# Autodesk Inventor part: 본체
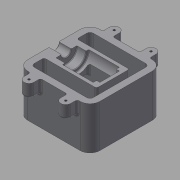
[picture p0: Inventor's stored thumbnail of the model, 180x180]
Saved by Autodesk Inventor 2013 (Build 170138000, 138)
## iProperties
Created: 2018-01
Part Number: 본체
Material: 일반
Document SubType Name: Modeling
Designer: Administrator
Density: 1 g/cm^3
Author: Administrator
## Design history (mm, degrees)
sketch "스케치1"
  geometry: L1 (-55, 55)-(55, 55); L2 (55, 55)-(55, -55); L3 (55, -55)-(-55, -55); L4 (-55, -55)-(-55, 55); L5 (-55, 55)-(55, -55); L6 (55, 55)-(-55, -55); 2 further points
  constraints: 12 end point, 4 midpoint, 2 parallel, 1 horizontal, 1 perpendicular
  dimensions: "d0" = 110 distance of L2.end L3.end; "d1" = 110 distance of L1.end L2.end
extrude "돌출1" new body sketch "스케치1" distance "d2" = 65; taper "d3" = 0 deg
fillet "모깎기1" dims "d4" = 15
sketch "스케치3"
  geometry: L1 (55, 40)-(55, -40) reference; L2 (40, -55)-(-40, -55) reference; L3 (-55, -40)-(-55, 40) reference; L4 (-40, 55)-(40, 55) reference; L5 (45, 40)-(45, -40); L6 (40, -45)-(-40, -45); L7 (-45, -40)-(-45, 40); L8 (-40, 45)-(40, 45); A1 r 15 centre (40, 40) between (55, 40) and (40, 55) reference; A2 r 15 centre (40, -40) between (40, -55) and (55, -40) reference; A3 r 15 centre (-40, -40) between (-55, -40) and (-40, -55) reference; A4 r 15 centre (-40, 40) between (-40, 55) and (-55, 40) reference; A5 r 5 centre (40, 40) between (45, 40) and (40, 45); A6 r 5 centre (40, -40) between (40, -45) and (45, -40); A7 r 5 centre (-40, -40) between (-45, -40) and (-40, -45); A8 r 5 centre (-40, 40) between (-40, 45) and (-45, 40); 1 further point
  constraints: 8 end point, 8 point on circle, 4 centre point, 7 other
  dimensions: "d5" = 10 distance between parallel lines of L1 L5
extrude "돌출2" cut sketch "스케치3" stored distance "d6" = 65; taper "d7" = 0 deg
sketch "스케치5"
  geometry: L1 (-35.5, 55)-(-35.5, 65); L2 (40, 55)-(-40, 55) reference; L3 (-20.5, 65)-(-20.5, 55); L4 (-55, 40)-(-55, -40) reference; L5 (0, 32.443)-(0, -32.443); L6 (35.5, 55)-(35.5, 65); L7 (20.5, 65)-(20.5, 55); L8 (-28, 0)-(28, 0); L9 (-40, -55)-(40, -55) reference; L10 (-35.5, 55)-(-20.5, 55); L11 (20.5, 55)-(35.5, 55); L12 (-20.5, -65)-(-20.5, -55); L13 (-35.5, -55)-(-35.5, -65); L14 (20.5, -65)-(20.5, -55); L15 (35.5, -55)-(35.5, -65); L16 (20.5, -55)-(35.5, -55); L17 (-35.5, -55)-(-20.5, -55); A1 r 7.5 centre (-28, 65) between (-20.5, 65) and (-35.5, 65); A2 r 7.5 centre (28, 65) between (35.5, 65) and (20.5, 65); A3 r 7.5 centre (-28, -65) between (-35.5, -65) and (-20.5, -65); A4 r 7.5 centre (28, -65) between (20.5, -65) and (35.5, -65); 2 further points
  constraints: 28 end point, 15 symmetric about line, 8 point on circle, 4 centre point, 3 parallel, 2 midpoint, 2 perpendicular, 2 point on line, 2 tangent, 1 coincident, 3 other
  dimensions: "d14" = 7.5 radius of A1; "d15" = 27 distance from line of A1.centre L4; "d16" = 10 distance of L3.start L3.end; "d17" = 64.88594 distance of L5.start L5.end; "d18" = 56 distance of L8.start L8.end
extrude "돌출4" join sketch "스케치5" distance "d19" = 20; taper "d20" = 0 deg
sketch "스케치6"
  geometry: A1 r 7.5 centre (-28, 65) between (-20.5, 65) and (-35.5, 65) reference; A2 r 7.5 centre (28, 65) between (35.5, 65) and (20.5, 65) reference; A3 r 7.5 centre (28, -65) between (20.5, -65) and (35.5, -65) reference; A4 r 7.5 centre (-28, -65) between (-35.5, -65) and (-20.5, -65) reference; 5 further points
  constraints: 4 coincident
hole "구멍1" sketch "스케치6" at (-28, 65), (28, 65), (-28, -65), (28, -65) diameter "d21" = 3.242; stored, may be unused: countersink angle "d25" = 90 deg, drill point angle "d27" = 118 deg; dims "d22" = 9, "d23" = 4, "d24" = 2, "d26" = 11
sketch "스케치8"
  geometry: L1 (-45, 25)-(35, 25); L2 (-45, -40)-(-45, 40) reference; L3 (35, 25)-(35, -25); L4 (35, -25)-(-45, -25); L5 (55, -40)-(55, 40) reference; L6 (-45, 25)-(-45, -25); 2 further points
  constraints: 8 end point, 2 perpendicular, 2 point on line, 1 collinear, 1 horizontal alignment, 1 midpoint, 1 parallel
  dimensions: "d28" = 20 distance between parallel lines of L5 L3; "d29" = 50 distance between parallel lines of L4 L1
extrude "돌출5" join sketch "스케치8" distance "d30" = 65; taper "d31" = 0 deg
sketch "스케치12"
  geometry: L1 (-55, 0)-(39.453, 0); L2 (-55, 40)-(-55, -40) reference; L3 (-45, 25)-(35, 25) reference; L4 (35, -25)-(-45, -25) reference; L5 (35, 25)-(35, -25) reference; L6 (-55, 7.5)-(-36, 7.5); L7 (-55, -40)-(-55, 40) reference; L8 (-36, 7.5)-(-36, 16); L9 (-36, 16)-(-22, 16); L10 (-22, 16)-(-22, 20); L11 (-22, 20)-(25, 20); L12 (25, 20)-(25, 15); L13 (25, 15)-(30, 15); L14 (30, 15)-(30, 0); L15 (-55, 7.5)-(-55, 0); 2 further points
  constraints: 20 end point, 5 parallel, 3 perpendicular, 3 point on line, 1 coincident, 1 collinear, 1 horizontal, 1 midpoint
  dimensions: "d32" = 15 diameter of L6 L1; "d34" = 32 diameter of L9 L1; "d35" = 40 diameter of L11 L1; "d37" = 30 diameter of L13 L1; "d38" = 19 distance of L6.start L6.end; "d39" = 14 distance of L8.end L9.end; "d40" = 47 distance of L10.end L11.end; "d41" = 5 distance of L12.end L13.end
revolve "회전1" sketch "스케치12" stored, may be unused: angle "d42" = 90 deg
sketch "스케치16"
  geometry: L1 (-20, 58.93)-(-20, 31.157); L2 (-35, 65)-(-35, 0) reference; L3 (-20, 31.157)-(55, 11.061); L4 (17, 58.93)-(17, 39.243); L5 (17, 39.243)-(55, 29.061); L6 (55, 65)-(55, 0) reference; L7 (-25, 45)-(22, 45) reference; L8 (35, 11.244)-(-35, 30); L9 (-25, 45)-(-25, 65) reference; L10 (-35, 0)-(45, 0) reference; L11 (35, 11.244)-(35, 0); L12 (55, 29.061)-(55, 11.061); L13 (-20, 58.93)-(17, 58.93); L14 (-20.5, 45)-(-20.5, 65) reference; 1 further point
  constraints: 16 end point, 4 point on line, 3 parallel, 2 perpendicular
  dimensions: "d43" = 75 deg angle of L6 L5; "d46" = 37 distance between parallel lines of L4 L1; "d48" = 18 distance of L3.end L5.end; "d49" = 5 distance between parallel lines of L1 L9; "d50" = 5 distance between parallel lines of L3 L8; "d51" = 105 deg angle of L6 L8; "d52" = 30 distance from line of L10 L8.end; "d53" = 20 distance between parallel lines of L6 L11; "d54" = 37 distance of L1.start L4.start (derived); "d55" = 19.68695 distance of L4.start L4.end
extrude "돌출6" cut sketch "스케치16" stored distance "d56" = 30; taper "d57" = 0 deg
sketch "스케치17"
  geometry: L1 (55, 11.061)-(-20, 31.157) reference; L2 (55, 65)-(55, 0) reference; L3 (17, 39.243)-(17, 45) reference; L4 (17, 45)-(22, 45) reference; L5 (22, 45)-(22, 49) reference; L6 (22, 49)-(36, 49) reference; L7 (36, 49)-(36, 57.5) reference; L8 (36, 57.5)-(55, 57.5) reference; L9 (55, 57.5)-(55, 29.061) reference; L10 (55, 29.061)-(17, 39.243) reference; L11 (-30, 65)-(-30, 50) reference; L12 (-30, 50)-(-25, 50) reference; L13 (-25, 50)-(-25, 45) reference; L14 (-25, 45)-(-20, 45) reference; L15 (-20, 45)-(-20, 31.157) reference; L16 (-20, 31.157)-(55, 11.061) reference; L17 (55, 11.061)-(55, 0) reference; L18 (55, 0)-(-35, 0) reference; L19 (-35, 0)-(-35, 65) reference; L20 (-35, 65)-(-30, 65) reference; L21 (-55, 65)-(-45, 65) reference; L22 (-45, 65)-(-45, 0) reference; L23 (-45, 0)-(-55, 0) reference; L24 (-55, 0)-(-55, 65) reference; L25 (45, 8.564)-(-35, 30); L26 (-35, 30)-(-35, 0); L27 (45, 8.564)-(45, 0); L28 (40, 0)-(40, 65) reference; 1 further point
  constraints: 6 end point, 3 parallel, 2 point on line
  dimensions: "d62" = 5 distance between parallel lines of L1 L25; "d64" = 30 distance from line of L18 L25.end; "d65" = 10 distance between parallel lines of L2 L27
extrude "돌출7" cut sketch "스케치17" stored distance "d66" = 50; taper "d67" = 0 deg
fillet "모깎기2" dims "d68" = 1
chamfer "모따기1" distance "d69" = 1; stored, may be unused: second distance "d70" = 2, angle "d71" = 45 deg
fillet "모깎기3" dims "d72" = 3
fillet "모깎기4" dims "d73" = 3
fillet "모깎기5" dims "d74" = 3
fillet "모깎기6" dims "d75" = 3
fillet "모깎기7" dims "d76" = 3
fillet "모깎기8" dims "d77" = 3
fillet "모깎기9" dims "d78" = 3
fillet "모깎기10" dims "d79" = 3
fillet "모깎기11" dims "d80" = 3
fillet "모깎기12" dims "d81" = 3
fillet "모깎기13" dims "d82" = 3
fillet "모깎기14" dims "d83" = 3
node "솔리드1"
node "절단 모서리 투영1"
node "절단 모서리 투영3"
